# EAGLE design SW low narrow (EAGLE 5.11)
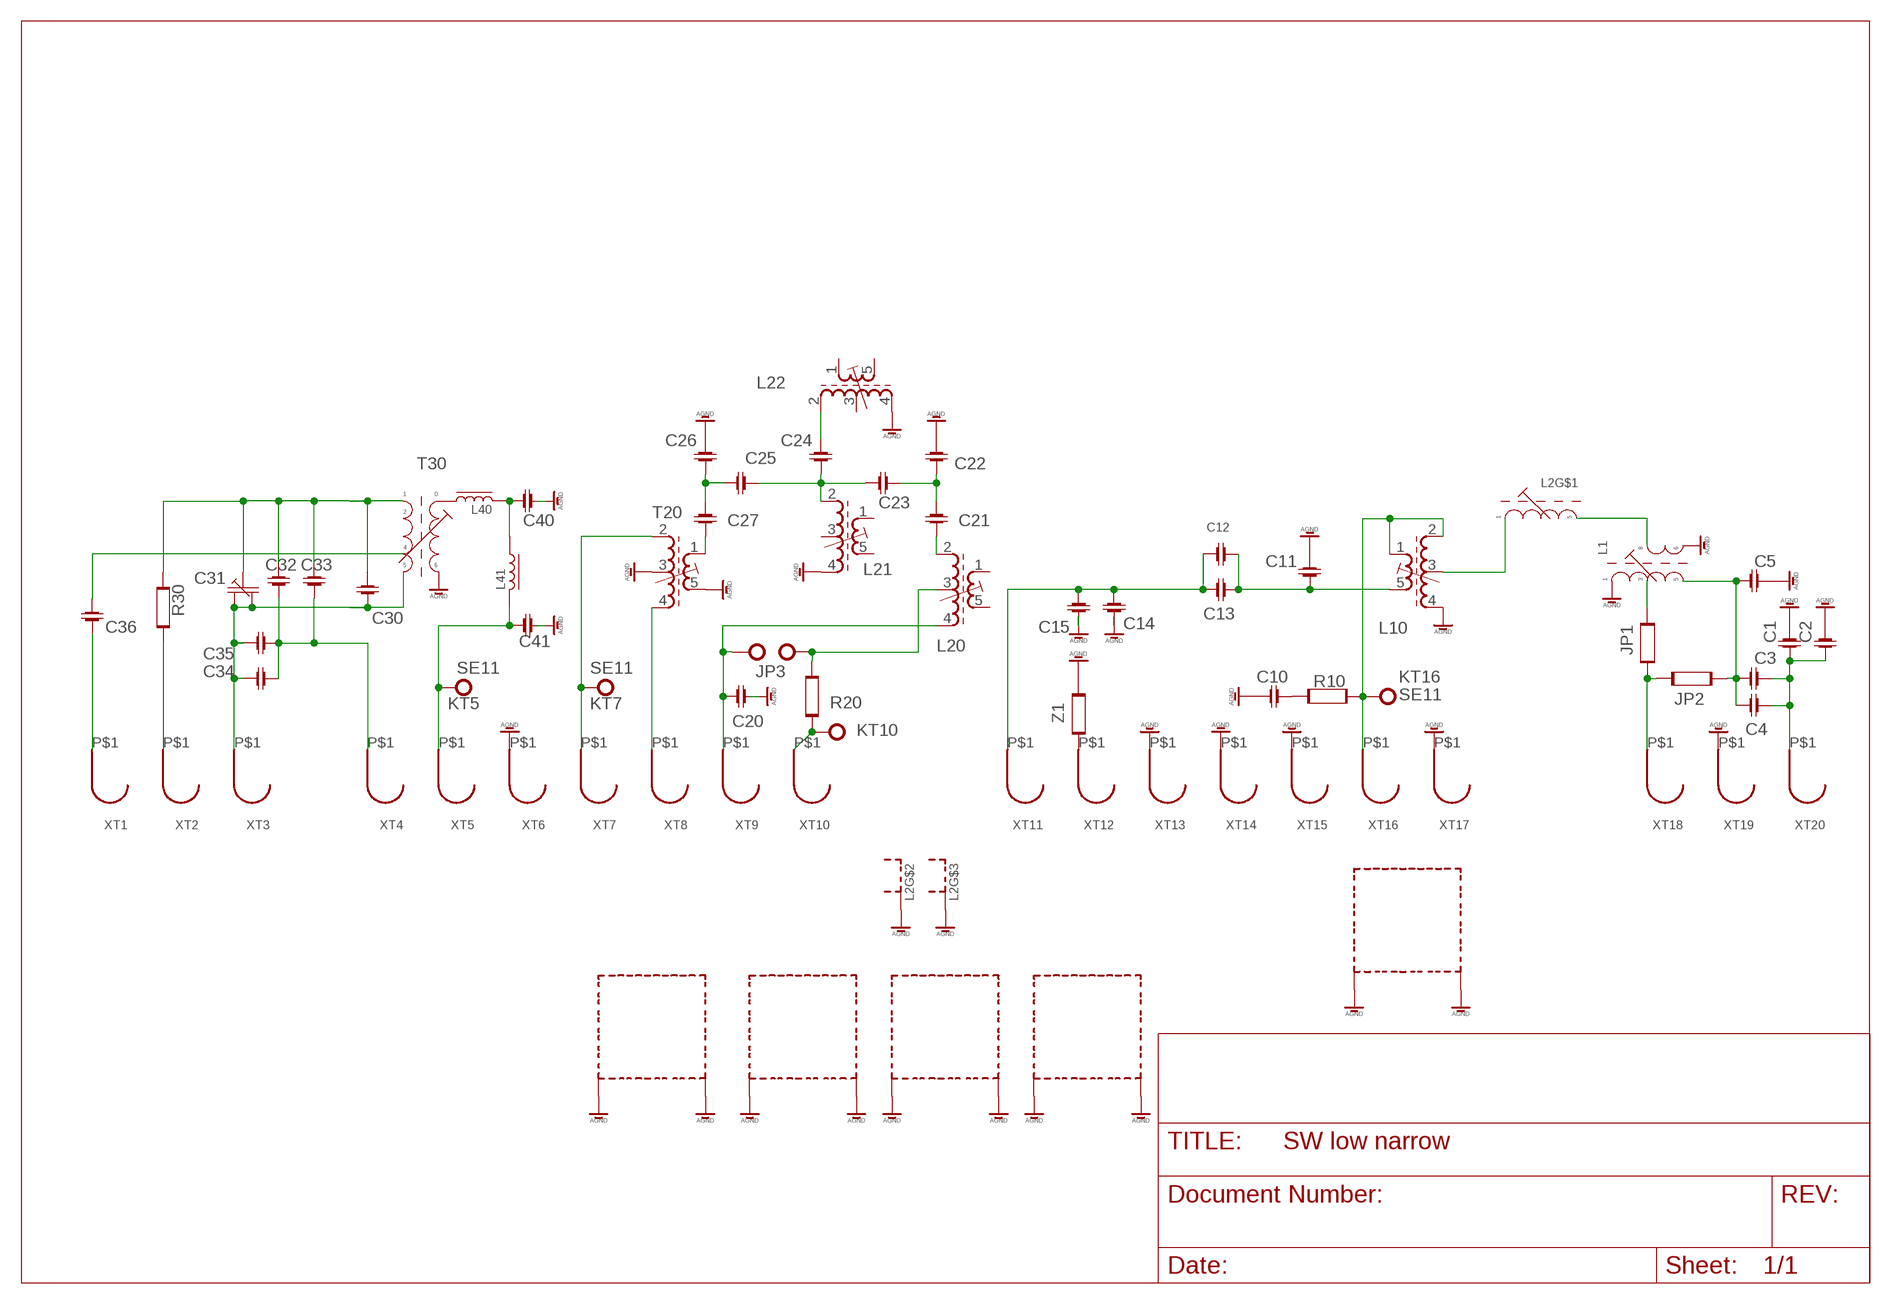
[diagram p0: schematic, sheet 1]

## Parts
C1  C-1206-0805  [RC-SMD-UNIV]
C2  C-1206-0805  [RC-SMD-UNIV]
C3  C-1206-0805  [RC-SMD-UNIV]
C4  C-1206-0805  [RC-SMD-UNIV]
C5  C-1206-0805  [RC-SMD-UNIV]
C10  C-1206-0805  [RC-SMD-UNIV]
C11  C-1206-0805  [RC-SMD-UNIV]
C12  C-1206-0805  [RC-SMD-UNIV]
C13  C-1206-0805  [RC-SMD-UNIV]
C14  C-1206-0805  [RC-SMD-UNIV]
C15  C-1206-0805  [RC-SMD-UNIV]
C20  C-1206-0805  [RC-SMD-UNIV]
C21  C-1206-0805  [RC-SMD-UNIV]
C22  C-1206-0805  [RC-SMD-UNIV]
C23  C-1206-0805  [RC-SMD-UNIV]
C24  C-1206-0805  [RC-SMD-UNIV]
C25  C-1206-0805  [RC-SMD-UNIV]
C26  C-1206-0805  [RC-SMD-UNIV]
C27  C-1206-0805  [RC-SMD-UNIV]
C30  C-1206-0805  [RC-SMD-UNIV]
C31  C-TRIM-AM  [C-TRIM-ORIG]
C32  C-1206-0805  [RC-SMD-UNIV]
C33  C-1206-0805  [RC-SMD-UNIV]
C34  C-1206-0805  [RC-SMD-UNIV]
C35  C-1206-0805  [RC-SMD-UNIV]
C36  C-1206-0805  [RC-SMD-UNIV]
C40  C-1206-0805  [RC-SMD-UNIV]
C41  C-1206-0805  [RC-SMD-UNIV]
JP1  R-1206-0805  [RC-SMD-UNIV]
JP2  R-1206-0805  [RC-SMD-UNIV]
JP3  SE11  [SE11]
KT1  SE11  [SE11]
KT5  SE11  [SE11]
KT7  SE11  [SE11]
KT10  SE11  [SE11]
KT16  SE11  [SE11]
L1  L-MOD-SW-IN-OPEN  [L-KW-LARGE]
L2  L-MOD-SW-GAP  [L-7-MM]
L10  71-5-24153  [71-5]
L20  71-5-24153  [71-5]
L21  71-5-24153  [71-5]
L22  71-5-24153  [71-5]
L40  L-US0207/10  [0207/10]
L41  L-US0207/10  [0207/10]
R10  R-1206-0805  [RC-SMD-UNIV]
R20  R-1206-0805  [RC-SMD-UNIV]
R30  R-1206-0805  [RC-SMD-UNIV]
T20  71-5-24153  [71-5]
T30  L-MOD-OSC-SW  [L-KW-LARGE]
XT1  CONTACT-RF  [CONTACT-RF]
XT2  CONTACT-RF  [CONTACT-RF]
XT3  CONTACT-RF  [CONTACT-RF]
XT4  CONTACT-RF  [CONTACT-RF]
XT5  CONTACT-RF  [CONTACT-RF]
XT6  CONTACT-RF  [CONTACT-RF]
XT7  CONTACT-RF  [CONTACT-RF]
XT8  CONTACT-RF  [CONTACT-RF]
XT9  CONTACT-RF  [CONTACT-RF]
XT10  CONTACT-RF  [CONTACT-RF]
XT11  CONTACT-RF  [CONTACT-RF]
XT12  CONTACT-RF  [CONTACT-RF]
XT13  CONTACT-RF  [CONTACT-RF]
XT14  CONTACT-RF  [CONTACT-RF]
XT15  CONTACT-RF  [CONTACT-RF]
XT16  CONTACT-RF  [CONTACT-RF]
XT17  CONTACT-RF  [CONTACT-RF]
XT18  CONTACT-RF  [CONTACT-RF]
XT19  CONTACT-RF  [CONTACT-RF]
XT20  CONTACT-RF  [CONTACT-RF]
Z1  R-1206-0805  [RC-SMD-UNIV]

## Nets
AGND: C1.P$2 C2.P$2 C5.P$2 C10.P$2 C11.P$1 C14.P$2 C15.P$1 C20.P$2 C22.P$2 C26.P$2 C40.P$1 C41.P$2 L1.P$2 L1.P$3 L2.P$6(S) L2.P$7(S) L10.4(E1) L10.S1 L10.S2 L20.S1 L20.S2 L21.4(E1) L21.S1 L21.S2 L22.4(E1) L22.S1 L22.S2 T20.3(Z) T20.5(E2) T20.S1 T20.S2 T30.P$2 XT6.P$1 XT13.P$1 XT14.P$1 XT15.P$1 XT17.P$1 XT19.P$1 Z1.P$2
KT1: KT16.MP L10.1(A2) L10.2(A1) R10.P$1 XT16.P$1
N$1: C1.P$1 C2.P$1 C3.P$2 C4.P$2 XT20.P$1
N$2: C10.P$1 R10.P$2
N$3: C20.P$1 KT1.MP L20.4(E1) XT9.P$1
N$4: JP1.P$1 JP2.P$2 XT18.P$1
N$5: T20.4(E1) XT8.P$1
N$6: L1.P$6 L2.3
N$7: C11.P$2 C12.P$2 C13.P$1 L10.5(E2)
N$9: JP3.MP L20.3(Z) R20.P$1
N$10: XT12.P$1 Z1.P$1
N$11: KT10.MP R20.P$2 XT10.P$1
N$12: C12.P$1 C13.P$2 C14.P$1 C15.P$2 XT11.P$1
N$13: KT7.MP T20.2(A1) XT7.P$1
N$14: C27.P$1 T20.1(A2)
N$15: C25.P$2 C26.P$1 C27.P$2
N$16: R30.P$2 XT2.P$1
N$18: L40.1 T30.P$3
N$19: C23.P$2 C24.P$1 C25.P$1 L21.2(A1)
N$20: C30.P$2 C31.P$6 C31.P$7 C34.P$2 C35.P$2 T30.P$6 XT3.P$1
N$21: C32.P$2 C33.P$2 C34.P$1 C35.P$1 XT4.P$1
N$22: C30.P$1 C31.P$5 C32.P$1 C33.P$1 R30.P$1 T30.P$5
N$23: C41.P$1 KT5.MP L41.2 XT5.P$1
N$24: C36.P$1 T30.P$4
N$25: C40.P$2 L40.2 L41.1
N$26: C36.P$2 XT1.P$1
N$28: C3.P$1 C4.P$1 C5.P$1 JP2.P$1 L1.P$1
N$29: C21.P$2 C22.P$1 C23.P$1
N$30: C21.P$1 L20.2(A1)
N$31: C24.P$2 L22.2(A1)
N$32: JP1.P$2 L1.P$5
N$35: L2.1 L10.3(Z)
Unconnected: L20.1(A2) L20.5(E2) L21.1(A2) L21.3(Z) L21.5(E2) L22.1(A2) L22.3(Z) L22.5(E2) T30.P$1

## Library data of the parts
C1-C5 C10-C15 C20-C27 C30 C32-C36 C40 C41 = OKEAH:C-1206-0805
C31 = OKEAH:C-TRIM-AM
JP1 JP2 R10 R20 R30 Z1 = OKEAH:R-1206-0805
JP3 KT1 KT5 KT7 KT10 KT16 = solpad:SE11: SOLDER PAD
L1 = OKEAH:L-MOD-SW-IN-OPEN
L2 = OKEAH:L-MOD-SW-GAP
L10 L20-L22 T20 = L NEOSID:71-5-: TRANSFORMER adjustable filter transformer with tap; OC_FARNELL: unknown; OC_NEWARK: unknown
L40 L41 = rcl:L-US: INDUCTOR, American symbol
T30 = OKEAH:L-MOD-OSC-SW
XT1-XT20 = OKEAH:CONTACT-RF

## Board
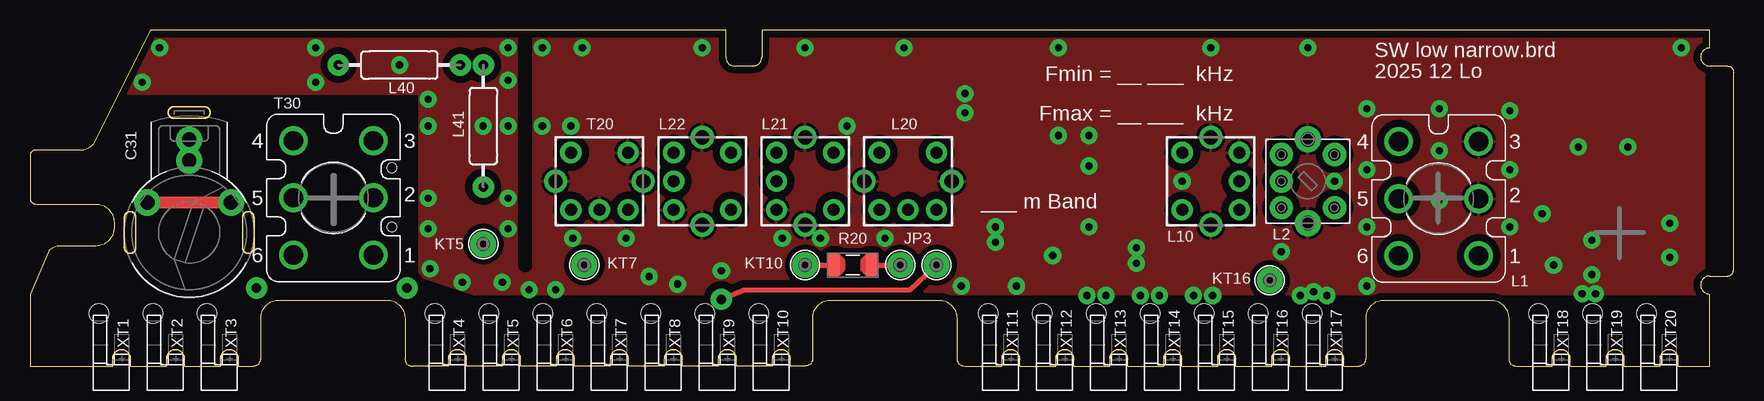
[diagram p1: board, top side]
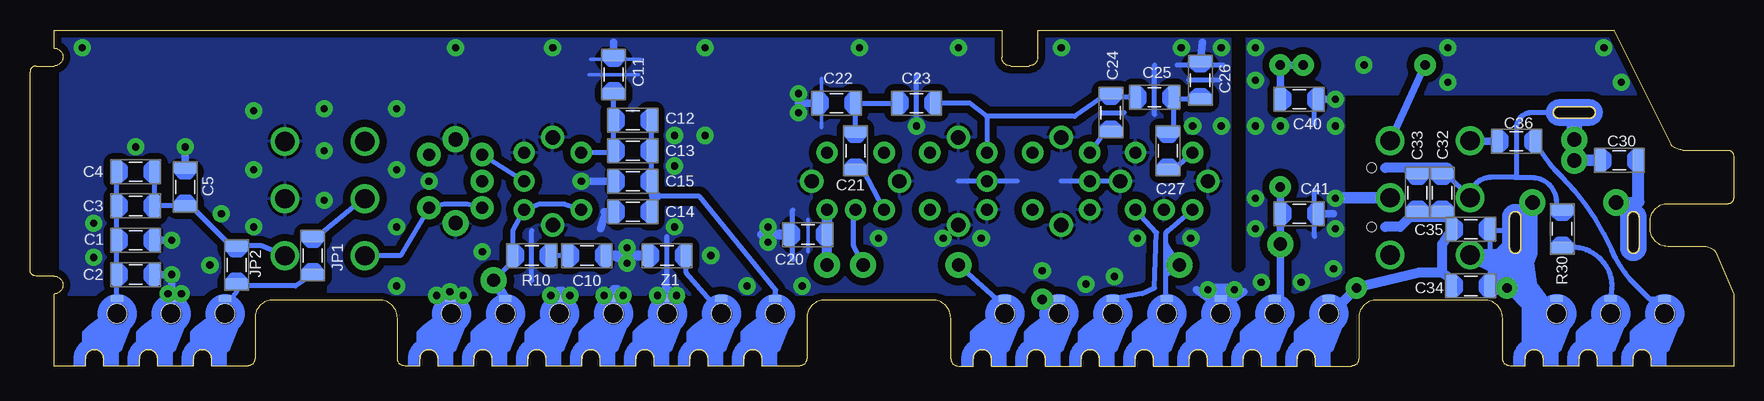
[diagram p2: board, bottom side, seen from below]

Size 142 x 28 mm. Coordinates in mm from the lower left corner, seen from the top.
Outline: 135 segments
Copper layers (1*16): Top 0.035mm / dielectric 1.5mm / Bottom 0.035mm
Design rules "default *": minimum track width 10mil, minimum drill 24mil, track to track 8mil, track to pad 8mil, pad to pad 8mil, via to via 8mil, smd to smd 8mil, copper to edge 8mil, drill to drill 8mil, minimum pad ring 10mil, minimum via ring 8mil, stop-mask expansion 4mil, vias tented up to drill 0mil, thermal gap 10mil
Holes 0.8 mm at 30.16,16.51 30.16,11.59
tRestrict: 2 lines
bRestrict: 18 lines

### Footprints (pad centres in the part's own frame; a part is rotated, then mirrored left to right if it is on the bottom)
RC-SMD-UNIV = smd 0.965 x 1.93: P$1 -1.587,0; P$2 1.587,0
C-TRIM-ORIG = drill 1.2 pad 2.184 round: P$4 7.739,0; P$5 5.992,0; P$6 2.5,3.493; P$7 2.5,-3.493
SE11 = drill 1.1 pad 2.159 round: MP 0,0
L-KW-LARGE = drill 1.6 round: P$1 0,0; P$2 0,4.763; P$3 0,9.525; P$4 -6.668,9.525; P$5 -6.668,4.763; P$6 -6.668,0
L-7-MM = drill 1 pad 1.93 round: 1 -2.223,-2.223; 2 0,-2.223; 3 2.223,-2.223; 4 2.223,2.223; 5 -2.223,2.223 | drill 1.2 pad 2.184 round: P$6 3.493,0; P$7 -3.493,0
71-5 = drill 1 pad 1.778 round: 1 2.381,-2.381; 2 2.381,2.381; 3 0,2.381; 4 -2.381,2.381; 5 -2.381,-2.381 | drill 1.2 pad 1.93 round: S1 -3.651,0; S2 3.651,0
0207/10 = drill 0.8 pad 1.778 round: 1 -5.08,0; 2 5.08,0
CONTACT-RF = smd 1.016 x 0.508 bottom: P$1 1,-5.625 | hole 1.6: 1,-4.375

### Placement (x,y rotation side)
C1  133.19,10.48 0 bottom
C2  133.19,7.62 0 bottom
C3  133.19,13.34 180 bottom
C4  133.19,16.19 180 bottom
C5  129.06,14.92 90 bottom
C10  95.57,9.21 0 bottom
C11  93.35,24.29 270 bottom
C12  91.76,20.48 180 bottom
C13  91.76,17.94 0 bottom
C14  91.76,12.86 180 bottom
C15  91.76,15.4 0 bottom
C20  77.15,10.96 180 bottom
C21  73.18,17.94 90 bottom
C22  74.77,21.91 180 bottom
C23  68.1,21.91 0 bottom
C24  51.91,21.12 270 bottom
C25  48.26,22.39 0 bottom
C26  44.45,23.81 90 bottom
C27  47.15,17.94 90 bottom
C30  9.53,17.15 0 bottom
C31  13.27,11.13 90 top
C32  24.29,14.45 270 bottom
C33  26.35,14.45 270 bottom
C34  21.91,6.67 0 bottom
C35  21.9,11.4 0 bottom
C36  18.1,18.73 0 bottom
C40  36.2,22.23 180 bottom
C41  36.2,12.7 0 bottom
JP1  118.43,9.21 90 bottom
JP2  124.78,8.42 270 bottom
JP3  72.55,8.42 0 top
KT1  75.56,8.42 0 top
KT5  37.78,10.16 0 top
KT7  46.2,8.42 0 top
KT10  64.61,8.42 0 top
KT16  103.35,7.15 0 top
L1  120.75,9.19 0 top
L2  106.52,15.4 270 top
L10  98.42,15.4 270 top
L20  73.18,15.4 180 top
L21  64.61,15.4 90 top
L22  56.04,15.4 90 top
L40  30.8,25.08 0 top
L41  37.78,20 270 top
R10  100.17,9.21 0 bottom
R20  68.58,8.42 180 top
R30  14.29,11.43 270 bottom
T20  47.47,15.4 180 top
T30  28.62,9.25 0 top
XT1  6.75,0 180 top
XT2  11.25,0 180 top
XT3  15.75,0 180 top
XT4  34.75,0 180 top
XT5  39.25,0 180 top
XT6  43.75,0 180 top
XT7  48.25,0 180 top
XT8  52.75,0 180 top
XT9  57.25,0 180 top
XT10  61.75,0 180 top
XT11  80.88,0 180 top
XT12  85.38,0 180 top
XT13  89.88,0 180 top
XT14  94.38,0 180 top
XT15  98.88,0 180 top
XT16  103.38,0 180 top
XT17  107.88,0 180 top
XT18  126.75,0 180 top
XT19  131.25,0 180 top
XT20  135.75,0 180 top
Z1  88.9,9.21 180 bottom

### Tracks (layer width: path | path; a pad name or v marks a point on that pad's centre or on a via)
AGND  (via drill 0.6 pad 1.42)
  Bottom 0.305: v107,6.19 v108.11,5.88 | 77.15,9.53 77.15,12.23 | 76.04,19.85 76.04,23.97 | 91.12,25.56 95.25,25.56 | 91.28,24.29 95.41,24.29
  Bottom 0.406: XT17.P$1 v107,6.19 | 34.92,20.16 34.92,22.39 | 34.92,10.8 34.92,14.61 | 78.42,8.89 78.42,13.02 | 48.26,20.96 48.26,25.08 | 68.1,19.85 68.1,24.29 | C10.P$2 93.82,9.21 v92.23,8.57 | 52.7,21.12 50.8,21.12 | 100.17,7.15 100.17,11.27 | 88.9,6.67 88.9,10.8 | T20.S1 56.04,15.4 | 59.69,15.4 64.61,15.4 | 42.86,23.82 45.4,23.82 | 42.55,25.09 46.35,25.09 | C11.P$1 | C11.P$1 93.34,25.4
  Bottom 0.61: 44.77,6.35 43.5,5.4 XT6.P$1 41.91,5.4 40.8,6.19 | C41.P$2 33.34,12.7 | C40.P$1 33.34,22.23 | C26.P$2 44.29,26.99 | C22.P$2 77.95,21.91 | C2.P$2 v130.18,7.62 130.18,5.72 XT19.P$1 | C1.P$2 v130.18,10.48 | C15.P$1 v96.04,15.4 | C14.P$2 94.14,12.86 93.66,12.39 94.14,12.39 94.46,11.43 | C5.P$2 v129.06,18.26 | 93.34,25.4 93.34,26.99
  Bottom 0.813: XT14.P$1 93.34,5.72 93.34,6.35 93.03,6.35 v92.55,5.88 | XT15.P$1 97.63,6.19 97.95,6.19 97.79,5.72 v97,5.88 | C20.P$2 80.96,10.96 | 88.11,6.03 89.06,6.35 89.06,6.03 v89.69,5.88 v88.11,5.88 XT13.P$1 | 93.82,9.21 Z1.P$2 93.82,9.21 | 93.82,9.21 94.14,9.21 93.82,9.21
  Bottom 1.016: T30.P$2 v33.18,13.97 | v41.59,6.35 v43.81,6.35
  other vias: 33.18,20 37.78,20 30.8,25.08 10.79,26.51 23.81,26.51 23.81,23.66 105.89,5.88 9.37,23.66 65.88,10.64 39.85,26.51 33.18,11.43 33.34,8.1 80.49,10.32 77.63,6.67 71.28,10.64 111.44,16.35 104.3,9.53 39.37,6.99 94.14,5.88 98.58,5.88 39.85,23.81 111.44,11.59 123.35,16.35 36.04,6.99 51.59,7.46 68.1,20 62.71,10.64 64.61,26.51 80.49,11.59 53.98,6.83 45.08,20 56.04,26.51 77.95,22.7 42.7,20 42.7,26.51 72.87,26.51 57.63,7.94 46.04,26.51 88.26,16.67 77.95,21.12 137.64,26.51 111.44,21.43 106.52,26.51 85.72,26.51 88.26,19.21 98.42,26.51 88.26,11.59 123.35,11.59 117.47,13.81 130.49,6.03 129.38,6.03 136.68,11.91 136.68,9.05 133.19,18.26 126.05,12.7 123.35,21.27 117.47,17.94 92.23,9.84 82.23,6.67 85.25,9.21 117.47,21.43 111.44,6.67 108.74,15.4 127,8.42 85.72,19.21 39.85,20 33.18,22.23 39.85,13.97 39.85,11.43 45.24,10.64 49.69,10.64
  pour Top (isolate 0.61): 37,6 32.5,7.5 32.5,22.68 7.5,22.68 10,28 58,28 58,25 61,25 61,28 139.5,28 139.5,6
  pour Bottom (isolate 0.61): 10,28 139.5,28 139.5,6 37,6 32.5,7.5 32.5,22.68 7.5,22.68
KT1
  Bottom 0.406: XT16.P$1 102.39,5.63 | KT16.MP 102.08,8.42 R10.P$1 101.76,11.27 L10.2 99.54,13.5 97.47,13.5 L10.1
  Bottom 0.813: KT16.MP XT16.P$1
N$1
  Bottom 0.406: XT20.P$1 134.78,5.72 C2.P$1 C1.P$1 C3.P$2 C4.P$2
N$2
  Bottom 0.406: C10.P$1 R10.P$2
N$3  (via drill 0.8 pad 1.78)
  Top 0.406: v57.63,5.56 59.53,6.35 73.34,6.35 75.41,8.26 KT1.MP
  Bottom 0.406: XT9.P$1 v57.63,5.56
  Bottom 0.813: 75.56,12.23 C20.P$1 | 75.56,12.23 L20.4 | KT1.MP 75.56,12.23
N$4
  Bottom 0.406: JP1.P$1 119.86,6.67 124.62,6.67 124.78,6.67 JP2.P$2 124.78,6.19 125.25,5.56 125.32,5.63 XT18.P$1
N$5
  Bottom 0.406: T20.4 48.1,11.12 48.26,6.51 49.37,6.03 XT8.P$1
N$6
  Bottom 0.406: L1.P$6 111.12,9.21 108.74,13.18 107.47,13.5 105.57,13.5 L2.3
N$7
  Bottom 0.406: L10.5 93.5,17.78 C13.P$1 C12.P$2 | C12.P$2 | C12.P$2 C11.P$2
N$9
  Top 0.406: R20.P$1 JP3.MP
  Bottom 0.406: JP3.MP 73.34,10 73.34,13.02 L20.3
N$10
  Bottom 0.406: XT12.P$1 85.25,5.4 87.31,7.78 Z1.P$1
N$11
  Top 0.406: KT10.MP 66.04,8.42 66.52,8.42 R20.P$2
  Bottom 0.406: KT10.MP 61.44,5.56 XT10.P$1
N$12
  Bottom 0.406: C12.P$1 C13.P$2 C15.P$2 90.17,14.77 | 90.17,14.13 90.17,13.5 | 90.17,13.5 C14.P$1 | 90.17,14.13 90.17,14.77 | XT11.P$1 79.85,6.35 86.2,14.13 89.53,14.13 | 89.53,14.13 90.17,14.13 | 89.53,14.13 90.17,13.5 | 89.53,14.13 90.17,14.77
N$13
  Bottom 0.406: 47.31,10.16 KT7.MP 46.67,7.94 | 47.31,10.16 47.31,11.12 47.15,11.27 T20.2 | XT7.P$1 47.31,5.72 47.31,5.88 47.31,7.62 | 47.31,7.62 46.67,7.94 | 47.31,7.62 47.31,10.16 | 46.67,7.94 47.15,9.53
N$14
  Bottom 0.406: C27.P$1 46.2,16.83 T20.1
N$15
  Bottom 0.406: C26.P$1 46.35,22.23 | 46.35,22.23 | 46.35,22.23 46.67,22.23 C25.P$2 46.67,22.07 46.67,21.91 46.67,19.53 46.99,19.53 C27.P$2
N$16
  Bottom 0.406: XT2.P$1 10.16,6.19 arc-37 10.48,8.1 arc-52 12.86,9.84 arc-21 R30.P$2
N$17
  Bottom 0.813: 23.81,16.35 23.81,16.51 29.05,16.51
N$18
  Bottom 0.61: T30.P$3 L40.1
N$19
  Bottom 0.406: C24.P$1 52.23,22.7 54.93,20.8 62.23,20.8 | 62.23,20.8 63.66,21.91 | 63.66,21.91 66.36,21.91 C23.P$2 | 62.23,20.8 63.66,21.91 | 62.23,20.8 L21.2 | C25.P$1 51.44,22.39 51.59,22.55 C24.P$1 | C24.P$1
N$20
  Top 1.016: C31.P$7 C31.P$6
  Bottom 0.406: 15.88,4.77 16.51,4.77 | 19.84,9.22 19.84,9.37 19.05,10.16 19.05,11.27 20.18,11.27 C35.P$2 C34.P$2
  Bottom 0.61: XT3.P$1 15.56,5.4 15.88,4.77
  Bottom 1.016: C30.P$2 7.94,13.65 C31.P$6 | 16.51,4.77 15.88,5.4 16.83,6.67 16.82,6.51 17.12,8.57 | 17.12,8.57 16.83,9.37 16.83,13.63 C31.P$7 | T30.P$6 19.84,9.22 19.37,9.21 19.37,8.57 17.12,8.57
  Bottom 1.27: 16.82,6.51 20.16,6.51
N$21  (via drill 0.8 pad 1.78)
  Bottom 0.406: C34.P$1 23.65,7.31 | XT4.P$1 32.7,5.24 v31.43,6.51
  Bottom 0.61: C35.P$1 23.81,12.86 C32.P$2 C33.P$2
  Bottom 0.813: C35.P$1 24.29,10.16 24.29,7.78 | 23.65,7.31 24.29,7.78 | 32.7,5.24 v31.43,6.51 26.19,7.78 24.29,7.78 | C32.P$2 24.29,12.7 23.97,12.39 26.99,12.39 | 26.99,12.39 | 26.99,12.39 27.78,11.59 29.05,11.59
N$22
  Bottom 0.406: R30.P$1 14.76,13.18 14.76,13.66 arc-90 16.83,15.72 18.26,15.72 | 18.26,15.72 20.25,15.72 arc-90 T30.P$5 23.89,15.94 arc-45 24.11,16.04 C32.P$1 | C31.P$5 13.27,20.17 arc-45 13.34,20.32 14.79,20.32 arc45 15.02,20.42 15.24,20.64 15.24,20.83 arc-45 15.33,21.05 15.4,21.12 16.83,21.12 arc-90 18.1,19.85 18.1,15.88 arc90 18.26,15.72
  Bottom 0.61: C32.P$1 24.77,16.19 25.72,16.19 C33.P$1
  Bottom 1.016: C30.P$1 C31.P$5
N$23
  Bottom 0.61: L41.2 C41.P$1 KT5.MP | KT5.MP 37.78,5.72 XT5.P$1 | KT5.MP 37.78,6.35
N$24
  Bottom 0.61: C36.P$1 20.95,18.74 T30.P$4
N$25
  Bottom 0.61: C40.P$2 L41.1 L40.2
N$26
  Bottom 0.406: XT1.P$1 6.35,5.56 6.85,5.56 arc45 7.08,5.65 8.1,6.67 arc21 10.16,9.69 arc-21 14.29,15.72 arc13 16.19,18.1 arc12 C36.P$2
N$27  (via drill 0.8 pad 1.78)
  Bottom 0.406: v18.89,6.51 19.37,6.51 19.37,6.99
  Bottom 1.016: 18.41,6.35 19.21,8.42 21.91,9.21 19.68,8.1 19.37,6.99 19.37,8.89 18.73,7.62 17.14,7.62 17.14,5.08 | 18.41,6.35 17.14,6.35 16.51,3.81 17.14,2.86 17.14,5.08 | 17.14,5.08 18.41,6.35
N$28
  Bottom 0.406: C4.P$1 C3.P$1 C5.P$1 128.27,13.02 125.25,10 JP2.P$1 124.14,10 122.71,10 L1.P$1
N$29
  Bottom 0.406: C23.P$1 73.03,21.91 C22.P$1 C21.P$2
N$30
  Bottom 0.406: L20.2 72.55,16.35 C21.P$1
N$31
  Bottom 0.406: L22.2 52.39,19.53 C24.P$2
N$32
  Bottom 0.406: L1.P$5 114.14,13.97 117.63,11.12 117.95,10.8 JP1.P$2
N$35
  Bottom 0.406: L10.3 L2.1

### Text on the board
tPlace: SW low narrow.brd | Fmin = __ ___ kHz | 2025 12 Lo | Fmax = __ ___ kHz | ___ m Band
tDocu: ANT Modul | grid placement = 0.125mm | grid placement = 0.125mm | grid SMD = 0.3175mm | grid SMD = 0.3175mm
